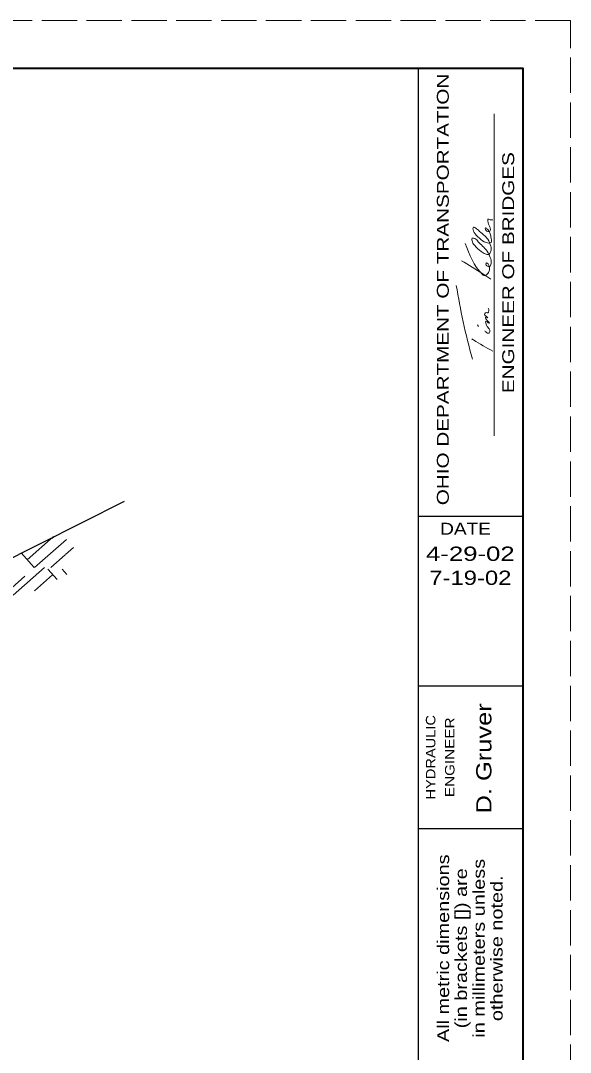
# Model space of a CAD drawing. Extents: x 1083.1 to 1117.1, y 672.5 to 716.5.
# Drawn here: x 1111.34 to 1117.13, y 705.66 to 716.51 of the extents above; entities that cross this region are included whole.
import ezdxf
from ezdxf.enums import TextEntityAlignment as Align

# ---------------------------------------------------------------- set-up
doc = ezdxf.new("R2010")
doc.units = 0
doc.header["$LTSCALE"] = 0.062
doc.linetypes.add('LONG_DASHED', pattern=[7.5, 6, -1.5])
doc.layers.add('1', color=7, linetype='Continuous', lineweight=13)

msp = doc.modelspace()

# ---------------------------------------------------------------- linework, layer by layer
at = {"layer": '1', "lineweight": 25}
for p, q in [((1085.12642, 716.00825), (1116.62642, 716.00825)), ((1115.52642, 695.00825), (1115.52642, 716.00825)), ((1116.62642, 716.00825), (1116.62642, 695.00825)), ((1107.83583, 709.13767), (1112.433, 711.45358)), ((1116.62642, 711.29242), (1115.52642, 711.29242)), ((1116.62642, 709.50825), (1115.52642, 709.50825)), ((1116.62642, 708.00825), (1115.52642, 708.00825))]:
    msp.add_line(p, q, dxfattribs=at)
at = {"layer": '1'}
for p, q in [((1116.32517, 712.13925), (1116.32517, 715.52933)), ((1116.15767, 713.29017), (1116.1475, 713.30942)), ((1111.41017, 710.83708), (1111.687, 711.08167)), ((1111.48658, 710.75458), (1111.82175, 711.05083)), ((1111.6695, 711.06017), (1111.68825, 711.07675)), ((1111.34608, 710.90958), (1111.48317, 710.75458)), ((1111.65625, 710.75458), (1111.80858, 710.88933)), ((1111.812, 710.89217), (1111.89625, 710.96667)), ((1111.26117, 710.46433), (1111.58917, 710.75458)), ((1111.48408, 710.51133), (1111.67392, 710.679)), ((1111.62725, 710.73833), (1111.72317, 710.62992)), ((1111.777, 710.73842), (1111.82733, 710.68158)), ((1111.24625, 710.54142), (1111.38558, 710.66475))]:
    msp.add_line(p, q, dxfattribs=at)
at = {"layer": '1', "linetype": 'LONG_DASHED'}
msp.add_lwpolyline([(1083.12642, 694.50825), (1117.12642, 694.50825), (1117.12642, 716.50825), (1083.12642, 716.50825)], close=True, dxfattribs=at)
at = {"layer": '1', "lineweight": 40}
msp.add_lwpolyline([(1085.12642, 716.00825), (1116.62642, 716.00825), (1116.62642, 695.00825), (1085.12642, 695.00825)], close=True, dxfattribs=at)
msp.add_lwpolyline([(1085.12642, 716.00825), (1116.62642, 716.00825), (1116.62642, 695.00825), (1085.12642, 695.00825)], close=True, dxfattribs=at)
at = {"layer": '1'}
for points in [[(1116.01825, 714.16525), (1116.20142, 713.83692), (1116.21658, 713.82633), (1116.22675, 713.82633), (1116.25867, 713.85), (1116.27375, 713.88417), (1116.26875, 713.93542), (1116.25183, 713.95725), (1116.23833, 713.95725), (1116.23658, 713.94425), (1116.24675, 713.92908), (1116.26025, 713.92067), (1116.27533, 713.92067), (1116.2905, 713.94225), (1116.29392, 713.96158), (1116.28367, 714.01692), (1116.20142, 714.13733), (1116.15592, 714.182), (1116.119, 714.21658), (1116.09383, 714.21875), (1116.09558, 714.18017), (1116.12075, 714.14142), (1116.188, 714.07908), (1116.23008, 714.05367), (1116.26375, 714.04917), (1116.28708, 714.07517), (1116.29392, 714.10933), (1116.28883, 714.13508), (1116.25867, 714.20825), (1116.22842, 714.24025), (1116.16783, 714.29367), (1116.13917, 714.3195), (1116.10567, 714.33475), (1116.10225, 714.30675), (1116.11233, 714.28092), (1116.1695, 714.221), (1116.24017, 714.17375), (1116.29217, 714.17608), (1116.2905, 714.23375), (1116.27867, 714.27667), (1116.26533, 714.30242), (1116.25517, 714.31317), (1116.23175, 714.32817), (1116.2335, 714.31108), (1116.26875, 714.28958), (1116.28367, 714.30033), (1116.27058, 714.354), (1116.262, 714.38192), (1116.25867, 714.39458), (1116.25867, 714.40742), (1116.25867, 714.41608), (1116.28367, 714.41392), (1116.30908, 714.41392)], [(1115.97942, 713.983), (1116.20317, 713.8455), (1116.28883, 713.78983)], [(1116.09567, 712.946), (1115.997, 713.34125), (1115.92575, 713.72358)], [(1116.22675, 713.24492), (1116.235, 713.23425), (1116.27217, 713.22133), (1116.27692, 713.25375), (1116.25183, 713.29017), (1116.23658, 713.32642), (1116.23658, 713.34567), (1116.25183, 713.33942), (1116.262, 713.32858), (1116.27217, 713.32425), (1116.2485, 713.35642), (1116.23658, 713.37142), (1116.2335, 713.38875), (1116.25692, 713.38217), (1116.2485, 713.39083), (1116.22333, 713.41867), (1116.2335, 713.43383), (1116.25025, 713.43583), (1116.25867, 713.43383), (1116.26875, 713.45517), (1116.262, 713.48308)], [(1116.31083, 713.03042), (1116.10567, 713.15042), (1116.09008, 713.16083)]]:
    msp.add_spline(points, degree=3, dxfattribs=at)

# ---------------------------------------------------------------- texts
for s, height, width, p in [('OHIO DEPARTMENT OF TRANSPORTATION', 0.125, 1.3, (1115.84633, 713.6805)), ('ENGINEER OF BRIDGES', 0.125, 1.3, (1116.53467, 713.85729)), ('D. Gruver', 0.16, 1.25, (1116.29517, 708.7475)), ('HYDRAULIC', 0.1, 1.15, (1115.7055, 708.75933)), ('ENGINEER', 0.1, 1.2, (1115.90642, 708.75937)), ('All metric dimensions', 0.125, 1.25, (1115.85025, 706.75033)), ('in millimeters unless', 0.125, 1.25, (1116.22525, 706.75037)), ('(in brackets []) are', 0.125, 1.25, (1116.03775, 706.75033)), ('otherwise noted.', 0.125, 1.25, (1116.41275, 706.75033))]:
    msp.add_text(s, height=height, rotation=90, dxfattribs=dict(at, width=width)).set_placement(p, align=Align.CENTER)
for s, height, width, p in [('DATE', 0.125, 1.2, (1116.02312, 711.101)), ('4-29-02', 0.15, 1.35, (1116.07342, 710.8255)), ('7-19-02', 0.15, 1.25, (1116.07346, 710.57242))]:
    msp.add_text(s, height=height, dxfattribs=dict(at, width=width)).set_placement(p, align=Align.CENTER)

doc.saveas('drawing.dxf')
